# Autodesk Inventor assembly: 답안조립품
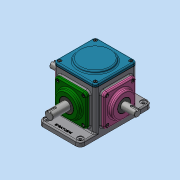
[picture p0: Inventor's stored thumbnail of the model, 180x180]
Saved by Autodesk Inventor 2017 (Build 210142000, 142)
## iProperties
Part Number: 답안조립품
Material: 일반
Document SubType Name: Assembly
Designer: MRC
Mass: 3235.88 g
Surface Area: 2651.66 cm^2
Volume: 866.536 cm^3
Density: 3.73427 g/cm^3
Author: MRC
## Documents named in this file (16)
- C:\Users\MRC\Desktop\620307V1013\답안조립품.iam
- C:\Users\MRC\Desktop\620307V1013\본체.ipt
- C:\Users\MRC\Desktop\620307V1013\개스킷.ipt
- C:\Users\MRC\Desktop\620307V1013\메인베벨기어.ipt
- C:\Users\MRC\Desktop\620307V1013\메인축.ipt
- C:\Users\MRC\Desktop\620307V1013\메인커버.ipt
- C:\Users\MRC\Desktop\620307V1013\베어링 6203.ipt
- C:\Users\MRC\Desktop\620307V1013\베어링 6204.ipt
- C:\Users\MRC\Desktop\620307V1013\볼트 M4.ipt
- C:\Users\MRC\Desktop\620307V1013\상부커버.ipt
- C:\Users\MRC\Desktop\620307V1013\서브베벨기어.ipt
- C:\Users\MRC\Desktop\620307V1013\서브축.ipt
- C:\Users\MRC\Desktop\620307V1013\서브커버.ipt
- C:\Users\MRC\Desktop\620307V1013\오일 실 17 32 8.ipt
- C:\Users\MRC\Desktop\620307V1013\오일 실 20 35 8.ipt
- C:\Users\MRC\Desktop\620307V1013\키 4x4.ipt
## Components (1 placed, 1 different names)
1. 개스킷:1
